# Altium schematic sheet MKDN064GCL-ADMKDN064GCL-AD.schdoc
size 127 x 101 mm
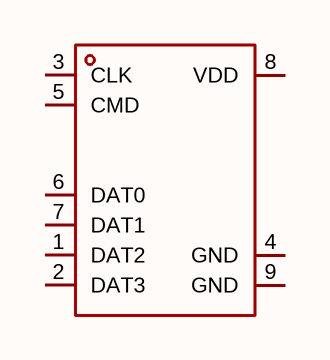
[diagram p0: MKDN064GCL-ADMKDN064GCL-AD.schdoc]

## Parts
U?  mkdn064gcl-ad  [LGA-16_L12.5-W9.0-P1.27-TL-EP]  (value not drawn)

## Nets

Not connected (* = marked no-connect by the designer): U? 1(DAT2) 2(DAT3) 3(CLK) 4(GND) 5(CMD) 6(DAT0) 7(DAT1) 8(VDD) 9(GND)

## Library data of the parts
U? = mkdn064gcl-ad: 存储容量:64Gbit;时钟频率(fc):208MHz;工作电压:2.7V~3.6V;; Manufacturer: MK(米客方德); AddInBom: yes; ModelId: aae4acadbbb4480ebd429fe2f08c27d7; ModelTransform: 492.125,354.33,0,0,0,0,0,0,0; Memory Size: 64Gbit; Interface: SD接口; Clock Frequency: 208MHz; Standby Supply Current: 80uA; ECC: 有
